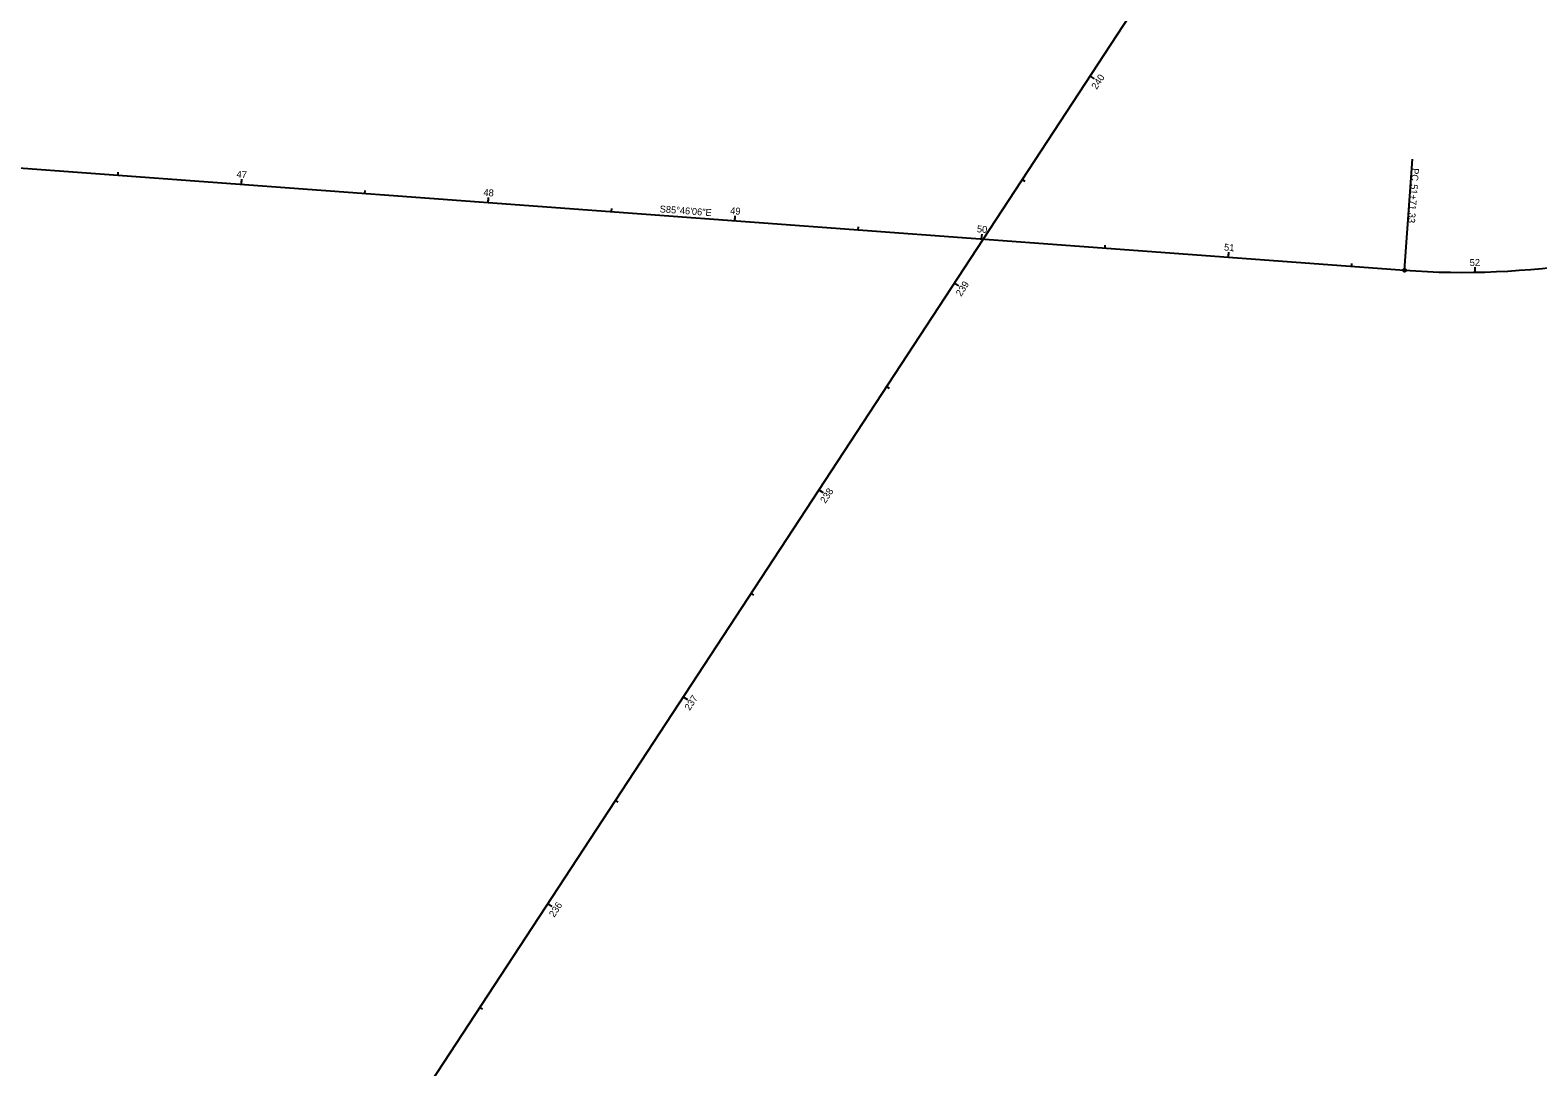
# Model space of a CAD drawing. Extents: x 1459328 to 1461822, y 481336 to 484746.
# Drawn here: x 1459944 to 1460553, y 482190 to 482609 of the extents above; entities that cross this region are included whole.
import ezdxf

# ---------------------------------------------------------------- set-up
doc = ezdxf.new("R2010")
doc.units = 0
for name, color, linetype in [('_CIVIL_CONSTRUCTION', 7, 'Continuous'), ('BR_X_SV_Abut', 7, 'Continuous'), ('DR_X_Ditch', 7, 'Continuous'), ('PV_X_EOP', 7, 'Continuous'), ('PV_X_Shoulder_Aggregate', 7, 'Continuous'), ('RD_X_GR_Lt', 7, 'Continuous'), ('RW_X_Esmt_SH', 7, 'Continuous'), ('SV_X_Break_Lines', 7, 'Continuous'), ('SV_X_Toe_of_Slope', 7, 'Continuous'), ('SV_X_Top_of_Bank', 7, 'Continuous'), ('UT_X_Electric_Cells', 7, 'Continuous'), ('UT_X_Sanitary_Cells', 7, 'Continuous')]:
    doc.layers.add(name, color=color, linetype=linetype)

msp = doc.modelspace()

# ---------------------------------------------------------------- linework, layer by layer
at = {"layer": '_CIVIL_CONSTRUCTION'}
msp.add_line((1459566.19, 481360.47), (1461783.98, 484745.51), dxfattribs=at)
at = {"layer": 'BR_X_SV_Abut'}
msp.add_line((1460499.29, 482512.29), (1460502.61, 482557.17), dxfattribs=at)
msp.add_circle((1460499.29, 482512.29), 0.6, dxfattribs=at)
at = {"layer": 'DR_X_Ditch'}
msp.add_line((1460372.23, 482590.75), (1460373.9, 482589.65), dxfattribs=at)
at = {"layer": 'PV_X_EOP'}
for p, q in [((1459979.38, 482550.76), (1459979.46, 482551.95)), ((1460029.24, 482547.07), (1460029.39, 482549.06)), ((1460079.1, 482543.38), (1460079.19, 482544.58)), ((1460128.97, 482539.69), (1460129.11, 482541.68)), ((1460178.83, 482536), (1460178.92, 482537.2)), ((1460228.69, 482532.31), (1460228.84, 482534.3)), ((1460278.56, 482528.62), (1460278.65, 482529.82)), ((1460328.42, 482524.93), (1460328.57, 482526.93)), ((1460378.28, 482521.24), (1460378.37, 482522.44)), ((1460428.15, 482517.55), (1460428.3, 482519.55)), ((1460478.01, 482513.86), (1460478.1, 482515.06)), ((1460527.93, 482511.46), (1460527.9, 482513.46))]:
    msp.add_line(p, q, dxfattribs=at)
at = {"layer": 'PV_X_Shoulder_Aggregate'}
msp.add_line((1460499.29, 482512.29), (1460502.61, 482557.17), dxfattribs=at)
msp.add_circle((1460499.29, 482512.29), 0.6, dxfattribs=at)
at = {"layer": 'RD_X_GR_Lt'}
msp.add_line((1460328.42, 482524.93), (1460328.57, 482526.93), dxfattribs=at)
at = {"layer": 'RW_X_Esmt_SH'}
msp.add_line((1459762.74, 482566.79), (1460499.29, 482512.29), dxfattribs=at)
msp.add_line((1459762.74, 482566.79), (1460499.29, 482512.29), dxfattribs=at)
msp.add_arc((1460522.77, 482829.73), 318.31, 265.76832, 292.51811, dxfattribs=at)
msp.add_arc((1460522.77, 482829.73), 318.31, 265.76832, 292.51811, dxfattribs=at)
at = {"layer": 'SV_X_Break_Lines'}
for p, q in [((1460029.24, 482547.07), (1460029.33, 482548.26)), ((1460128.97, 482539.69), (1460129.06, 482540.89)), ((1460228.69, 482532.31), (1460228.78, 482533.51)), ((1460328.42, 482524.93), (1460328.57, 482526.93)), ((1460428.15, 482517.55), (1460428.24, 482518.75)), ((1460527.93, 482511.46), (1460527.91, 482512.66))]:
    msp.add_line(p, q, dxfattribs=at)
at = {"layer": 'SV_X_Top_of_Bank'}
msp.add_line((1460499.29, 482512.29), (1460502.61, 482557.17), dxfattribs=at)
msp.add_circle((1460499.29, 482512.29), 0.6, dxfattribs=at)
at = {"layer": 'UT_X_Electric_Cells'}
for p, q in [((1460372.23, 482590.75), (1460373.9, 482589.65)), ((1460344.83, 482548.92), (1460345.83, 482548.27)), ((1460317.43, 482507.1), (1460319.1, 482506.01)), ((1460290.03, 482465.28), (1460291.03, 482464.62)), ((1460262.63, 482423.46), (1460264.3, 482422.36)), ((1460235.22, 482381.63), (1460236.23, 482380.97)), ((1460207.82, 482339.81), (1460209.5, 482338.71)), ((1460180.42, 482297.99), (1460181.43, 482297.33)), ((1460153.02, 482256.16), (1460154.69, 482255.07)), ((1460125.62, 482214.34), (1460126.62, 482213.68))]:
    msp.add_line(p, q, dxfattribs=at)
at = {"layer": 'UT_X_Sanitary_Cells'}
for p, q in [((1460372.23, 482590.75), (1460373.9, 482589.65)), ((1460317.43, 482507.1), (1460318.43, 482506.44)), ((1460262.63, 482423.46), (1460263.63, 482422.8)), ((1460207.82, 482339.81), (1460208.83, 482339.15)), ((1460153.02, 482256.16), (1460154.02, 482255.51))]:
    msp.add_line(p, q, dxfattribs=at)

# ---------------------------------------------------------------- texts
at = {"layer": 'BR_X_SV_Abut'}
for s, p in [('PC', (1460502.39, 482553.64)), ('51+71.33', (1460501.91, 482547.14))]:
    msp.add_text(s, height=2.8, rotation=265.76832, dxfattribs=at).set_placement(p)
at = {"layer": 'DR_X_Ditch'}
msp.add_text('240', height=2.8, rotation=56.76822, dxfattribs=at).set_placement((1460374.87, 482585.1))
at = {"layer": 'PV_X_EOP'}
for s, rotation, p in [('47', 355.76832, (1460027.18, 482549.73)), ('48', 355.76832, (1460126.97, 482542.39)), ('49', 355.76832, (1460226.72, 482535.01)), ('50', 355.76832, (1460326.42, 482527.63)), ('51', 355.76832, (1460426.32, 482520.24)), ('52', 0.92865, (1460525.71, 482513.97))]:
    msp.add_text(s, height=2.8, rotation=rotation, dxfattribs=at).set_placement(p)
at = {"layer": 'PV_X_Shoulder_Aggregate'}
for s, p in [('PC', (1460502.39, 482553.64)), ('51+71.33', (1460501.91, 482547.14))]:
    msp.add_text(s, height=2.8, rotation=265.76832, dxfattribs=at).set_placement(p)
at = {"layer": 'RD_X_GR_Lt'}
msp.add_text('50', height=2.8, rotation=355.76832, dxfattribs=at).set_placement((1460326.42, 482527.63))
at = {"layer": 'SV_X_Break_Lines'}
msp.add_text('50', height=2.8, rotation=355.76832, dxfattribs=at).set_placement((1460326.42, 482527.63))
at = {"layer": 'SV_X_Toe_of_Slope'}
msp.add_text('S85°46\'06"E', height=2.8, rotation=355.76832, dxfattribs=at).set_placement((1460198.22, 482535.7))
at = {"layer": 'SV_X_Top_of_Bank'}
for s, p in [('PC', (1460502.39, 482553.64)), ('51+71.33', (1460501.91, 482547.14))]:
    msp.add_text(s, height=2.8, rotation=265.76832, dxfattribs=at).set_placement(p)
at = {"layer": 'UT_X_Electric_Cells'}
for s, p in [('240', (1460374.87, 482585.1)), ('239', (1460320.08, 482501.48)), ('238', (1460265.26, 482417.81)), ('237', (1460210.43, 482334.11)), ('236', (1460155.65, 482250.51))]:
    msp.add_text(s, height=2.8, rotation=56.76822, dxfattribs=at).set_placement(p)
at = {"layer": 'UT_X_Sanitary_Cells'}
msp.add_text('240', height=2.8, rotation=56.76822, dxfattribs=at).set_placement((1460374.87, 482585.1))

doc.saveas('drawing.dxf')
